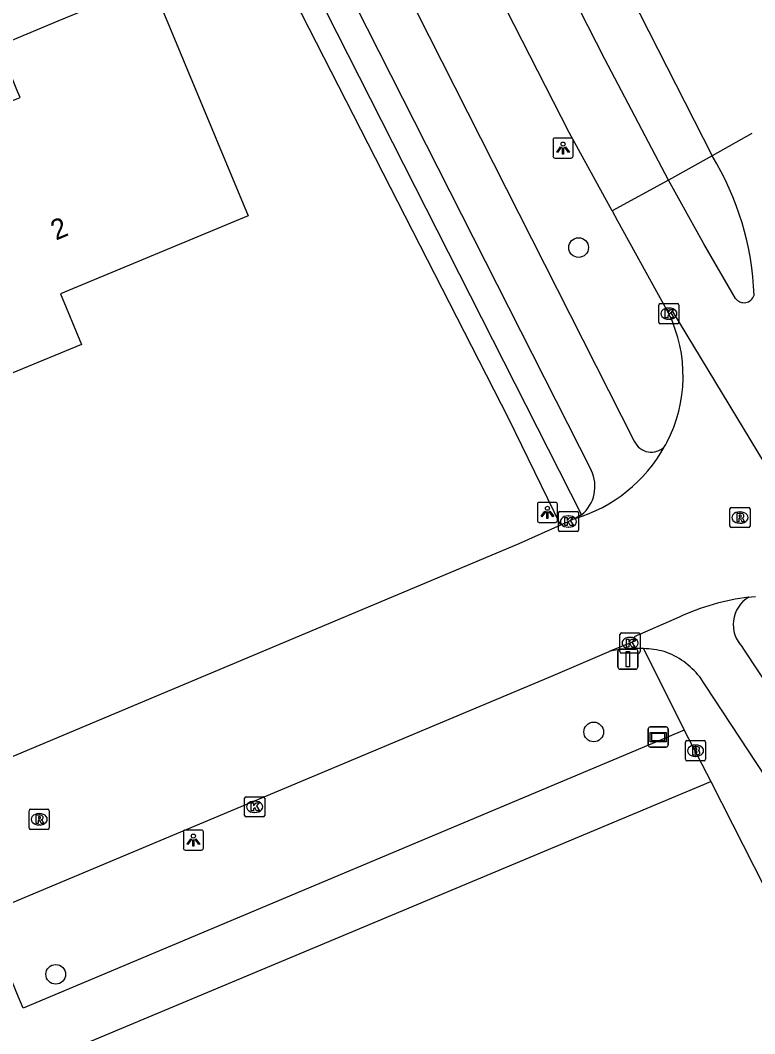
# Model space of a CAD drawing. Extents: x 162417 to 163721, y 384268 to 385416.
# Drawn here: x 163500.2 to 163536.6, y 385033 to 385083.3 of the extents above; entities that cross this region are included whole.
import ezdxf

# ---------------------------------------------------------------- set-up
doc = ezdxf.new("R2010")
doc.units = 0
for name, color, linetype in [('IMGEO_Boom', 7, 'Continuous'), ('IMGEO_Brandkraan', 7, 'Continuous'), ('IMGEO_Fietspad_open', 7, 'Continuous'), ('IMGEO_Kolk', 7, 'Continuous'), ('IMGEO_Lichtpunt', 7, 'Continuous'), ('IMGEO_Loofbos', 7, 'Continuous'), ('IMGEO_Pand', 7, 'Continuous'), ('IMGEO_Pand_nummerreeks', 7, 'Continuous'), ('IMGEO_Rijbaan_lokaal_gesloten', 7, 'Continuous'), ('IMGEO_Rioolput', 7, 'Continuous'), ('IMGEO_Verkeersbordpaal', 7, 'Continuous'), ('IMGEO_Verkeerseiland_open', 7, 'Continuous'), ('IMGEO_Verklikker', 7, 'Continuous'), ('IMGEO_Voetpad_open', 7, 'Continuous')]:
    doc.layers.add(name, color=color, linetype=linetype)

msp = doc.modelspace()

# ---------------------------------------------------------------- linework, layer by layer
at = {"layer": 'IMGEO_Boom'}
for centre in [(163527.879, 385072.011), (163528.628, 385047.969), (163501.923, 385035.94)]:
    msp.add_circle(centre, 0.489, dxfattribs=at)
at = {"layer": 'IMGEO_Brandkraan'}
for p, q in [((163533.182, 385046.612), (163533.182, 385047.464)), ((163533.257, 385047.538), (163534.109, 385047.538)), ((163533.67, 385047.318), (163533.695, 385047.318)), ((163534.183, 385047.464), (163534.183, 385046.612)), ((163533.693, 385046.758), (163533.668, 385046.758)), ((163534.109, 385046.538), (163533.257, 385046.538))]:
    msp.add_line(p, q, dxfattribs=at)
for points in [[(163533.182, 385046.612), (163533.182, 385047.464)], [(163533.257, 385047.538), (163534.109, 385047.538)], [(163533.53, 385047.238), (163533.53, 385046.838), (163533.743, 385046.838)], [(163533.761, 385047.238), (163533.53, 385047.238)], [(163533.709, 385047.157), (163533.655, 385047.157), (163533.655, 385047.081)], [(163533.655, 385047.081), (163533.708, 385047.081)], [(163534.183, 385047.464), (163534.183, 385046.612)], [(163533.717, 385047.005), (163533.655, 385047.005), (163533.655, 385046.924)], [(163533.655, 385046.924), (163533.717, 385046.924)], [(163534.109, 385046.538), (163533.257, 385046.538)]]:
    msp.add_lwpolyline(points, dxfattribs=at)
for centre, radius, start, end in [((163533.259, 385047.462), 0.0765, 91.552, 178.448), ((163533.259, 385047.462), 0.0765, 91.552, 178.448), ((163533.71, 385047.119), 0.0379, 267.8285, 90.9355), ((163533.765, 385047.093), 0.145, 59.4692, 91.5367), ((163533.79, 385047.14), 0.0922, 285.5137, 58.1501), ((163534.107, 385047.462), 0.0765, 1.552, 88.448), ((163534.107, 385047.462), 0.0765, 1.552, 88.448), ((163533.259, 385046.614), 0.0765, 181.552, 268.448), ((163533.259, 385046.614), 0.0765, 181.552, 268.448), ((163533.718, 385046.964), 0.0404, 269.8759, 90.5077), ((163533.749, 385047.089), 0.251, 268.6676, 293.5347), ((163533.795, 385046.948), 0.105, 301.3115, 78.989), ((163534.107, 385046.614), 0.0765, 271.552, 358.448), ((163534.107, 385046.614), 0.0765, 271.552, 358.448)]:
    msp.add_arc(centre, radius, start, end, dxfattribs=at)
for centre, major_axis, ratio, start_param, end_param in [((163533.669, 385047.038), (-0.387, 0.002), 0.722429, 4.712389, 7.853982), ((163533.694, 385047.038), (-0.39, 0.002), 0.717154, 1.570796, 4.712389)]:
    msp.add_ellipse(centre, major_axis=major_axis, ratio=ratio, start_param=start_param, end_param=end_param, dxfattribs=at)
at = {"layer": 'IMGEO_Fietspad_open'}
for points in [[(163431.787, 385208.07), (163431.922, 385207.954), (163432.159, 385207.714), (163433.841, 385205.808), (163444.2, 385193.223), (163470.237, 385163.265), (163478.767, 385152.569), (163484.279, 385144.583), (163488.178, 385138.38), (163494.183, 385128.236), (163502.766, 385111.711), (163507.809, 385101.794), (163517.384, 385082.877), (163528.502, 385060.963)], [(163503.289, 385116.398), (163530.645, 385062.397)], [(163528.022, 385058.738), (163527.71, 385058.563)]]:
    msp.add_lwpolyline(points, dxfattribs=at)
for centre, radius, start, end in [((163531.481, 385062.772), 0.916, 204.1377, 316.1565), ((163526.862, 385060.153), 1.829, 309.3524, 26.2999)]:
    msp.add_arc(centre, radius, start, end, dxfattribs=at)
at = {"layer": 'IMGEO_Kolk'}
for p, q in [((163531.934, 385069.23), (163532.786, 385069.23)), ((163531.859, 385068.304), (163531.859, 385069.156)), ((163532.347, 385069.01), (163532.372, 385069.01)), ((163532.86, 385069.156), (163532.86, 385068.304)), ((163532.786, 385068.23), (163531.934, 385068.23)), ((163532.37, 385068.45), (163532.345, 385068.45)), ((163526.873, 385057.988), (163526.873, 385058.84)), ((163526.948, 385058.914), (163527.8, 385058.914)), ((163527.361, 385058.694), (163527.386, 385058.694)), ((163527.874, 385058.84), (163527.874, 385057.988)), ((163527.384, 385058.134), (163527.359, 385058.134)), ((163527.8, 385057.914), (163526.948, 385057.914)), ((163529.933, 385051.957), (163529.933, 385052.809)), ((163530.008, 385052.883), (163530.86, 385052.883)), ((163530.421, 385052.663), (163530.446, 385052.663)), ((163530.934, 385052.809), (163530.934, 385051.957)), ((163530.444, 385052.103), (163530.419, 385052.103)), ((163530.86, 385051.883), (163530.008, 385051.883)), ((163511.296, 385043.828), (163511.296, 385044.68)), ((163511.371, 385044.754), (163512.223, 385044.754)), ((163512.297, 385044.68), (163512.297, 385043.828)), ((163511.784, 385044.534), (163511.809, 385044.534)), ((163512.223, 385043.754), (163511.371, 385043.754)), ((163511.807, 385043.974), (163511.782, 385043.974))]:
    msp.add_line(p, q, dxfattribs=at)
for points in [[(163531.934, 385069.23), (163532.786, 385069.23)], [(163531.859, 385068.304), (163531.859, 385069.156)], [(163532.18, 385068.93), (163532.303, 385068.93), (163532.303, 385068.779), (163532.433, 385068.93), (163532.597, 385068.93), (163532.451, 385068.779), (163532.604, 385068.53), (163532.452, 385068.53), (163532.367, 385068.694), (163532.303, 385068.627), (163532.303, 385068.53), (163532.18, 385068.53), (163532.18, 385068.93)], [(163532.86, 385069.156), (163532.86, 385068.304)], [(163532.786, 385068.23), (163531.934, 385068.23)], [(163526.873, 385057.988), (163526.873, 385058.84)], [(163526.948, 385058.914), (163527.8, 385058.914)], [(163527.874, 385058.84), (163527.874, 385057.988)], [(163527.194, 385058.614), (163527.317, 385058.614), (163527.317, 385058.463), (163527.447, 385058.614), (163527.611, 385058.614), (163527.465, 385058.463), (163527.618, 385058.214), (163527.466, 385058.214), (163527.381, 385058.378), (163527.317, 385058.311), (163527.317, 385058.214), (163527.194, 385058.214), (163527.194, 385058.614)], [(163527.8, 385057.914), (163526.948, 385057.914)], [(163529.933, 385051.957), (163529.933, 385052.809)], [(163530.008, 385052.883), (163530.86, 385052.883)], [(163530.934, 385052.809), (163530.934, 385051.957)], [(163530.254, 385052.583), (163530.377, 385052.583), (163530.377, 385052.432), (163530.507, 385052.583), (163530.671, 385052.583), (163530.525, 385052.432), (163530.678, 385052.183), (163530.526, 385052.183), (163530.441, 385052.347), (163530.377, 385052.28), (163530.377, 385052.183), (163530.254, 385052.183), (163530.254, 385052.583)], [(163530.86, 385051.883), (163530.008, 385051.883)], [(163511.296, 385043.828), (163511.296, 385044.68)], [(163511.371, 385044.754), (163512.223, 385044.754)], [(163512.297, 385044.68), (163512.297, 385043.828)], [(163511.617, 385044.454), (163511.74, 385044.454), (163511.74, 385044.303), (163511.87, 385044.454), (163512.034, 385044.454), (163511.888, 385044.303), (163512.041, 385044.054), (163511.889, 385044.054), (163511.804, 385044.218), (163511.74, 385044.151), (163511.74, 385044.054), (163511.617, 385044.054), (163511.617, 385044.454)], [(163512.223, 385043.754), (163511.371, 385043.754)]]:
    msp.add_lwpolyline(points, dxfattribs=at)
for centre, start, end in [((163531.936, 385069.154), 91.552, 178.448), ((163531.936, 385069.154), 91.552, 178.448), ((163532.784, 385069.154), 1.552, 88.448), ((163532.784, 385069.154), 1.552, 88.448), ((163531.936, 385068.306), 181.552, 268.448), ((163531.936, 385068.306), 181.552, 268.448), ((163532.784, 385068.306), 271.552, 358.448), ((163532.784, 385068.306), 271.552, 358.448), ((163526.95, 385058.838), 91.552, 178.448), ((163526.95, 385058.838), 91.552, 178.448), ((163527.798, 385058.838), 1.552, 88.448), ((163527.798, 385058.838), 1.552, 88.448), ((163526.95, 385057.99), 181.552, 268.448), ((163526.95, 385057.99), 181.552, 268.448), ((163527.798, 385057.99), 271.552, 358.448), ((163527.798, 385057.99), 271.552, 358.448), ((163530.01, 385052.807), 91.552, 178.448), ((163530.01, 385052.807), 91.552, 178.448), ((163530.858, 385052.807), 1.552, 88.448), ((163530.858, 385052.807), 1.552, 88.448), ((163530.01, 385051.959), 181.552, 268.448), ((163530.01, 385051.959), 181.552, 268.448), ((163530.858, 385051.959), 271.552, 358.448), ((163530.858, 385051.959), 271.552, 358.448), ((163511.373, 385044.678), 91.552, 178.448), ((163511.373, 385044.678), 91.552, 178.448), ((163512.221, 385044.678), 1.552, 88.448), ((163512.221, 385044.678), 1.552, 88.448), ((163511.373, 385043.83), 181.552, 268.448), ((163511.373, 385043.83), 181.552, 268.448), ((163512.221, 385043.83), 271.552, 358.448), ((163512.221, 385043.83), 271.552, 358.448)]:
    msp.add_arc(centre, 0.0765, start, end, dxfattribs=at)
for centre, major_axis, ratio, start_param, end_param in [((163532.346, 385068.73), (-0.387, 0.002), 0.722429, 4.712389, 7.853982), ((163532.371, 385068.73), (-0.39, 0.002), 0.717154, 1.570796, 4.712389), ((163527.36, 385058.414), (-0.387, 0.002), 0.722429, 4.712389, 7.853982), ((163527.385, 385058.414), (-0.39, 0.002), 0.717154, 1.570796, 4.712389), ((163530.42, 385052.383), (-0.387, 0.002), 0.722429, 4.712389, 7.853982), ((163530.445, 385052.383), (-0.39, 0.002), 0.717154, 1.570796, 4.712389), ((163511.783, 385044.254), (-0.387, 0.002), 0.722429, 4.712389, 7.853982), ((163511.808, 385044.254), (-0.39, 0.002), 0.717154, 1.570796, 4.712389)]:
    msp.add_ellipse(centre, major_axis=major_axis, ratio=ratio, start_param=start_param, end_param=end_param, dxfattribs=at)
at = {"layer": 'IMGEO_Lichtpunt'}
for p, q in [((163526.608, 385077.353), (163526.608, 385076.546)), ((163526.608, 385077.353), (163526.608, 385076.546)), ((163527.51, 385077.448), (163526.702, 385077.448)), ((163527.51, 385077.448), (163526.702, 385077.448)), ((163527.604, 385076.546), (163527.604, 385077.353)), ((163527.604, 385076.546), (163527.604, 385077.353)), ((163526.702, 385076.452), (163527.51, 385076.452)), ((163526.702, 385076.452), (163527.51, 385076.452)), ((163525.833, 385059.271), (163525.833, 385058.464)), ((163525.833, 385059.271), (163525.833, 385058.464)), ((163526.735, 385059.366), (163525.927, 385059.366)), ((163526.735, 385059.366), (163525.927, 385059.366)), ((163526.829, 385058.464), (163526.829, 385059.271)), ((163526.829, 385058.464), (163526.829, 385059.271)), ((163525.927, 385058.37), (163526.735, 385058.37)), ((163525.927, 385058.37), (163526.735, 385058.37)), ((163509.159, 385043.101), (163508.351, 385043.101)), ((163509.159, 385043.101), (163508.351, 385043.101)), ((163508.257, 385043.006), (163508.257, 385042.199)), ((163508.257, 385043.006), (163508.257, 385042.199)), ((163509.253, 385042.199), (163509.253, 385043.006)), ((163509.253, 385042.199), (163509.253, 385043.006)), ((163508.351, 385042.105), (163509.159, 385042.105)), ((163508.351, 385042.105), (163509.159, 385042.105))]:
    msp.add_line(p, q, dxfattribs=at)
for points in [[(163526.982, 385077.017), (163527.021, 385076.989), (163526.833, 385076.727), (163526.795, 385076.754), (163526.982, 385077.017)], [(163527.084, 385076.969), (163527.131, 385076.969), (163527.131, 385076.647), (163527.084, 385076.647), (163527.084, 385076.969)], [(163527.194, 385076.989), (163527.232, 385077.016), (163527.419, 385076.754), (163527.38, 385076.726), (163527.194, 385076.989)], [(163526.207, 385058.935), (163526.246, 385058.907), (163526.058, 385058.645), (163526.02, 385058.672), (163526.207, 385058.935)], [(163526.309, 385058.887), (163526.356, 385058.887), (163526.356, 385058.565), (163526.309, 385058.565), (163526.309, 385058.887)], [(163526.419, 385058.907), (163526.457, 385058.934), (163526.644, 385058.672), (163526.605, 385058.644), (163526.419, 385058.907)], [(163508.631, 385042.67), (163508.67, 385042.642), (163508.482, 385042.38), (163508.444, 385042.407), (163508.631, 385042.67)], [(163508.733, 385042.622), (163508.78, 385042.622), (163508.78, 385042.3), (163508.733, 385042.3), (163508.733, 385042.622)], [(163508.843, 385042.642), (163508.881, 385042.669), (163509.068, 385042.407), (163509.029, 385042.379), (163508.843, 385042.642)]]:
    msp.add_lwpolyline(points, dxfattribs=at)
for centre in [(163527.107, 385077.151), (163526.332, 385059.069), (163508.756, 385042.804)]:
    msp.add_circle(centre, 0.0994, dxfattribs=at)
for centre, start, end in [((163526.702, 385077.353), 90, 180), ((163526.702, 385077.353), 90, 180), ((163527.51, 385077.353), 0, 90), ((163527.51, 385077.353), 0, 90), ((163526.702, 385076.546), 180, 270), ((163526.702, 385076.546), 180, 270), ((163527.51, 385076.546), 270, 0), ((163527.51, 385076.546), 270, 360), ((163525.927, 385059.271), 90, 180), ((163525.927, 385059.271), 90, 180), ((163526.735, 385059.271), 0, 90), ((163526.735, 385059.271), 0, 90), ((163525.927, 385058.464), 180, 270), ((163525.927, 385058.464), 180, 270), ((163526.735, 385058.464), 270, 0), ((163526.735, 385058.464), 270, 360), ((163508.351, 385043.006), 90, 180), ((163508.351, 385043.006), 90, 180), ((163509.159, 385043.006), 0, 90), ((163509.159, 385043.006), 0, 90), ((163508.351, 385042.199), 180, 270), ((163508.351, 385042.199), 180, 270), ((163509.159, 385042.199), 270, 0), ((163509.159, 385042.199), 270, 360)]:
    msp.add_arc(centre, 0.0946, start, end, dxfattribs=at)
at = {"layer": 'IMGEO_Loofbos'}
msp.add_lwpolyline([(163357.745, 384991.405), (163354.406, 385000), (163343.981, 385026.826), (163371.144, 385038.583), (163419.878, 385059.084), (163500, 385092.556), (163507.868, 385095.856), (163524.402, 385063.53), (163526.981, 385058.237)], dxfattribs=at)
at = {"layer": 'IMGEO_Pand'}
msp.add_lwpolyline([(163500, 385082.41), (163502.045, 385083.258), (163506.663, 385085.173), (163511.47, 385073.585), (163502.16, 385069.723), (163503.203, 385067.206), (163500, 385065.878), (163495.882, 385064.17), (163493.966, 385068.789), (163491.098, 385075.704), (163500, 385079.397), (163500.156, 385079.461), (163500, 385079.838), (163499.09, 385082.032), (163500, 385082.41)], dxfattribs=at)
at = {"layer": 'IMGEO_Rijbaan_lokaal_gesloten'}
for points in [[(163529.538, 385073.829), (163527.411, 385077.727), (163506.761, 385118.162)], [(163516.524, 385111.893), (163534.501, 385076.568)], [(163532.346, 385075.361), (163529.186, 385081.36), (163515.061, 385109.044), (163514.998, 385109.228)], [(163536.486, 385077.671), (163534.501, 385076.568)], [(163532.346, 385075.361), (163529.538, 385073.829)], [(163535.665, 385069.49), (163534.102, 385072.198), (163532.346, 385075.361)], [(163529.538, 385073.829), (163529.802, 385073.345), (163532.363, 385068.727)], [(163532.363, 385068.727), (163532.534, 385068.831), (163543.443, 385050.842), (163543.272, 385050.738)], [(163532.142, 385062.137), (163532.206, 385062.231), (163532.264, 385062.331)], [(163526.981, 385058.237), (163524.917, 385057.312), (163500, 385046.827), (163425.932, 385015.904), (163388.243, 385000), (163387.545, 384999.704), (163359.186, 384987.697)], [(163527.71, 385058.563), (163526.981, 385058.237)], [(163536.323, 385054.66), (163536.468, 385054.673), (163536.657, 385054.689)], [(163532.866, 385053.668), (163530.635, 385052.693), (163530.708, 385052.491), (163529.399, 385051.967)], [(163498.926, 385039.152), (163505.769, 385042.017), (163526.498, 385050.73), (163529.399, 385051.967)]]:
    msp.add_lwpolyline(points, dxfattribs=at)
for centre, radius, start, end in [((163522.448, 385069.16), 14.148, 1.9545, 31.573), ((163536.088, 385069.796), 0.522, 215.8926, 342.9514), ((163525.894, 385065.628), 7.173, 332.631, 25.5954), ((163525.563, 385065.761), 7.511, 286.6115, 331.1545), ((163537.796, 385043.006), 11.747, 97.2052, 114.8168)]:
    msp.add_arc(centre, radius, start, end, dxfattribs=at)
at = {"layer": 'IMGEO_Rioolput'}
for p, q in [((163535.389, 385058.185), (163535.389, 385059.037)), ((163535.464, 385059.111), (163536.316, 385059.111)), ((163535.877, 385058.891), (163535.902, 385058.891)), ((163536.39, 385059.037), (163536.39, 385058.185)), ((163535.9, 385058.331), (163535.875, 385058.331)), ((163536.316, 385058.111), (163535.464, 385058.111)), ((163500.602, 385043.21), (163500.602, 385044.062)), ((163500.677, 385044.136), (163501.529, 385044.136)), ((163501.603, 385044.062), (163501.603, 385043.21)), ((163501.09, 385043.916), (163501.115, 385043.916)), ((163501.529, 385043.136), (163500.677, 385043.136)), ((163501.113, 385043.356), (163501.088, 385043.356))]:
    msp.add_line(p, q, dxfattribs=at)
for points in [[(163535.389, 385058.185), (163535.389, 385059.037)], [(163535.464, 385059.111), (163536.316, 385059.111)], [(163535.978, 385058.809), (163535.726, 385058.811), (163535.726, 385058.411)], [(163535.904, 385058.73), (163535.85, 385058.73), (163535.85, 385058.649)], [(163535.85, 385058.649), (163535.902, 385058.649)], [(163536.39, 385059.037), (163536.39, 385058.185)], [(163535.726, 385058.411), (163535.85, 385058.411), (163535.85, 385058.573), (163535.861, 385058.573)], [(163535.908, 385058.544), (163535.979, 385058.411), (163536.119, 385058.411), (163536.054, 385058.537)], [(163536.316, 385058.111), (163535.464, 385058.111)], [(163500.602, 385043.21), (163500.602, 385044.062)], [(163500.677, 385044.136), (163501.529, 385044.136)], [(163501.603, 385044.062), (163501.603, 385043.21)], [(163501.191, 385043.834), (163500.939, 385043.836), (163500.939, 385043.436)], [(163500.939, 385043.436), (163501.063, 385043.436), (163501.063, 385043.598), (163501.074, 385043.598)], [(163501.117, 385043.755), (163501.063, 385043.755), (163501.063, 385043.674)], [(163501.063, 385043.674), (163501.115, 385043.674)], [(163501.121, 385043.569), (163501.192, 385043.436), (163501.332, 385043.436), (163501.267, 385043.562)], [(163501.529, 385043.136), (163500.677, 385043.136)]]:
    msp.add_lwpolyline(points, dxfattribs=at)
for centre, radius, start, end in [((163535.466, 385059.035), 0.0765, 91.552, 178.448), ((163535.466, 385059.035), 0.0765, 91.552, 178.448), ((163535.886, 385058.838), 0.19, 274.7715, 282.9687), ((163535.91, 385058.634), 0.0964, 77.0061, 93.1865), ((163535.924, 385058.691), 0.0378, 276.6634, 79.6772), ((163535.977, 385058.699), 0.109, 350.3612, 89.416), ((163535.975, 385058.699), 0.112, 277.5842, 350.9817), ((163536.314, 385059.035), 0.0765, 1.552, 88.448), ((163536.314, 385059.035), 0.0765, 1.552, 88.448), ((163535.466, 385058.187), 0.0765, 181.552, 268.448), ((163535.466, 385058.187), 0.0765, 181.552, 268.448), ((163535.86, 385058.52), 0.0533, 26.0293, 88.6989), ((163535.959, 385058.484), 0.108, 29.5134, 73.7905), ((163536.314, 385058.187), 0.0765, 271.552, 358.448), ((163536.314, 385058.187), 0.0765, 271.552, 358.448), ((163500.679, 385044.06), 0.0765, 91.552, 178.448), ((163500.679, 385044.06), 0.0765, 91.552, 178.448), ((163501.527, 385044.06), 0.0765, 1.552, 88.448), ((163501.527, 385044.06), 0.0765, 1.552, 88.448), ((163501.073, 385043.545), 0.0533, 26.0293, 88.6989), ((163501.099, 385043.863), 0.19, 274.7715, 282.9687), ((163501.123, 385043.659), 0.0964, 77.0061, 93.1865), ((163501.137, 385043.716), 0.0378, 276.6634, 79.6772), ((163501.19, 385043.724), 0.109, 350.3612, 89.416), ((163501.188, 385043.724), 0.112, 277.5842, 350.9817), ((163501.172, 385043.509), 0.108, 29.5134, 73.7905), ((163500.679, 385043.212), 0.0765, 181.552, 268.448), ((163500.679, 385043.212), 0.0765, 181.552, 268.448), ((163501.527, 385043.212), 0.0765, 271.552, 358.448), ((163501.527, 385043.212), 0.0765, 271.552, 358.448)]:
    msp.add_arc(centre, radius, start, end, dxfattribs=at)
for centre, major_axis, ratio, start_param, end_param in [((163535.876, 385058.611), (-0.387, 0.002), 0.722429, 4.712389, 7.853982), ((163535.901, 385058.611), (-0.39, 0.002), 0.717154, 1.570796, 4.712389), ((163501.089, 385043.636), (-0.387, 0.002), 0.722429, 4.712389, 7.853982), ((163501.114, 385043.636), (-0.39, 0.002), 0.717154, 1.570796, 4.712389)]:
    msp.add_ellipse(centre, major_axis=major_axis, ratio=ratio, start_param=start_param, end_param=end_param, dxfattribs=at)
at = {"layer": 'IMGEO_Verkeersbordpaal'}
for p, q in [((163529.827, 385051.185), (163529.827, 385051.985)), ((163529.827, 385051.985), (163529.827, 385051.185)), ((163529.927, 385052.085), (163530.717, 385052.085)), ((163530.717, 385052.085), (163529.927, 385052.085)), ((163530.817, 385051.985), (163530.817, 385051.185)), ((163530.817, 385051.185), (163530.817, 385051.985)), ((163530.717, 385051.085), (163529.927, 385051.085)), ((163529.927, 385051.085), (163530.717, 385051.085))]:
    msp.add_line(p, q, dxfattribs=at)
msp.add_lwpolyline([(163530.247, 385051.96), (163530.397, 385051.96), (163530.397, 385051.21), (163530.247, 385051.21), (163530.247, 385051.96)], dxfattribs=at)
for centre, start, end in [((163529.927, 385051.985), 90, 180), ((163529.927, 385051.985), 90, 180), ((163530.717, 385051.985), 0, 90), ((163530.717, 385051.985), 360, 90), ((163529.927, 385051.185), 180, 270), ((163529.927, 385051.185), 180, 270), ((163530.717, 385051.185), 270, 0), ((163530.717, 385051.185), 270, 0)]:
    msp.add_arc(centre, 0.1, start, end, dxfattribs=at)
at = {"layer": 'IMGEO_Verkeerseiland_open'}
msp.add_lwpolyline([(163534.501, 385076.568), (163532.346, 385075.361)], dxfattribs=at)
at = {"layer": 'IMGEO_Verklikker'}
for p, q in [((163531.333, 385047.318), (163531.333, 385048.118)), ((163531.333, 385048.118), (163531.333, 385047.318)), ((163531.433, 385048.218), (163532.223, 385048.218)), ((163532.223, 385048.218), (163531.433, 385048.218)), ((163532.323, 385048.118), (163532.323, 385047.318)), ((163532.323, 385047.318), (163532.323, 385048.118)), ((163532.223, 385047.218), (163531.433, 385047.218)), ((163531.433, 385047.218), (163532.223, 385047.218))]:
    msp.add_line(p, q, dxfattribs=at)
for points in [[(163531.434, 385047.95), (163532.222, 385047.95), (163532.222, 385047.486), (163531.434, 385047.486), (163531.434, 385047.95)], [(163531.499, 385047.885), (163531.499, 385047.551), (163532.157, 385047.551), (163532.157, 385047.885), (163531.499, 385047.885)]]:
    msp.add_lwpolyline(points, dxfattribs=at)
for centre, start, end in [((163531.433, 385048.118), 90, 180), ((163531.433, 385048.118), 90, 180), ((163532.223, 385048.118), 0, 90), ((163532.223, 385048.118), 360, 90), ((163531.433, 385047.318), 180, 270), ((163531.433, 385047.318), 180, 270), ((163532.223, 385047.318), 270, 0), ((163532.223, 385047.318), 270, 0)]:
    msp.add_arc(centre, 0.1, start, end, dxfattribs=at)
at = {"layer": 'IMGEO_Voetpad_open'}
for points in [[(163500.985, 385111.712), (163505.392, 385103.355), (163528.022, 385058.738)], [(163531.103, 385052.107), (163533.125, 385048.062)], [(163540.948, 385044.731), (163536.021, 385052.178)], [(163574.621, 384973.481), (163547.457, 385026.967), (163540.137, 385041.23), (163534.186, 385050.269), (163533.893, 385050.706)], [(163533.125, 385048.062), (163500.305, 385034.267), (163500, 385035.007), (163498.937, 385037.584)], [(163533.125, 385048.062), (163534.443, 385045.503)], [(163363.507, 384973.847), (163365.371, 384974.629), (163425.859, 385000), (163500, 385031.078), (163534.443, 385045.503)], [(163534.443, 385045.503), (163557.559, 385000), (163571.782, 384971.962), (163572.96, 384969.64), (163599.332, 384917.655), (163619.201, 384879.411), (163644.977, 384828.162)]]:
    msp.add_lwpolyline(points, dxfattribs=at)
for centre, radius, start, end in [((163537.137, 385053.302), 1.584, 120.9328, 225.1924), ((163530.754, 385045.919), 6.198, 86.7693, 102.6244), ((163530.763, 385045.851), 6.265, 77.4684, 86.8859), ((163530.766, 385048.188), 4.015, 38.8389, 70.2573)]:
    msp.add_arc(centre, radius, start, end, dxfattribs=at)

# ---------------------------------------------------------------- texts
at = {"layer": 'IMGEO_Pand_nummerreeks'}
msp.add_text('2', height=1, rotation=22.5298, dxfattribs=at).set_placement((163501.933, 385072.356))

doc.saveas('drawing.dxf')
